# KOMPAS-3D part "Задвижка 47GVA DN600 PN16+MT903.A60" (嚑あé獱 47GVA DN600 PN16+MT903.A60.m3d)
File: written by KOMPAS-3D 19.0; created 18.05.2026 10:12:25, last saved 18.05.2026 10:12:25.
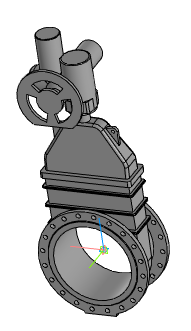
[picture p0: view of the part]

Document properties: Автор: Энергия; Полное имя файла: ..\Задвижка 47GVA DN40_DN1000+MT903.A\Задвижка 47GVA DN600 PN16+MT903.A60.a3d

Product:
- Part/product: Задвижка 47GVA DN600 PN16+MT903.A60
    Масса: 1298.63
  - Body: Электропривод МТ903.А60 без блока управления
      Масса: 346.451
  - Body: Задвижка 47GVA DN600 PN16 без исполнительного механизма
      Масса: 952.177

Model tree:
1. Операция без истории:1
2. Операция без истории:2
